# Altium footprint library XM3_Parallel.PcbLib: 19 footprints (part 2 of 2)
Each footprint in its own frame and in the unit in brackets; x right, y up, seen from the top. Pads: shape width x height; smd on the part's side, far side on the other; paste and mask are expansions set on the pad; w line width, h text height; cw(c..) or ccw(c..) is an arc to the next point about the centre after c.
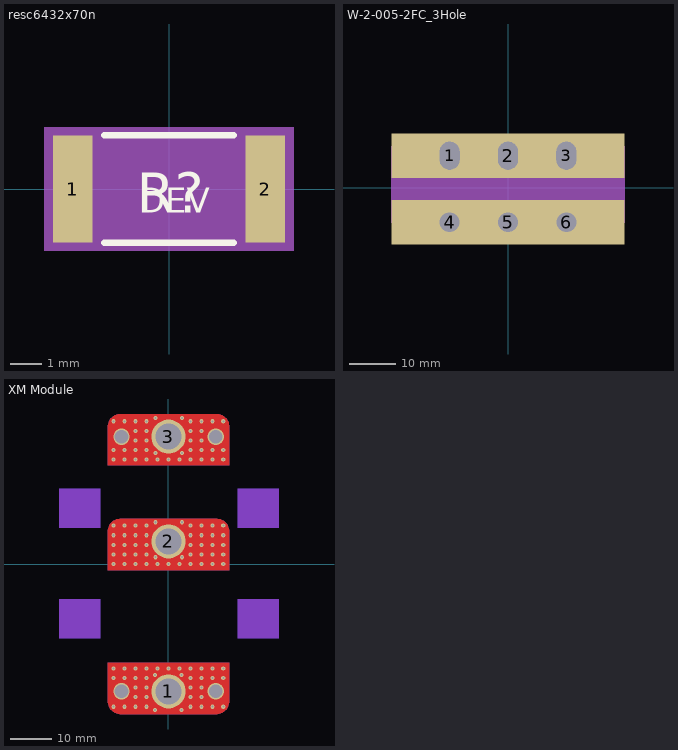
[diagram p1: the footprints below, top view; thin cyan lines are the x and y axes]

## resc6432x70n [mil]
pads (2):
  rect 49.21x133.86 smd: 1(-120.08,0) 2(120.08,0)
Top Overlay:
  lines w8: -80.71,-66.93 80.71,-66.93 ; -80.71,66.93 80.71,66.93
  text "DEV" at -37.2,-29.53 h31
  text "R?" at -40,-29.53 h50
DFA_BOUND_TOP:
  region: -155.51,-76.77 155.51,-76.77 155.51,76.77 -155.51,76.77
PLACE_BOUND_TOP:
  region: -155.51,-76.77 155.51,-76.77 155.51,76.77 -155.51,76.77
DISPLAY_TOP:
  lines w0.04: -129.92,-66.93 129.92,-66.93 129.92,66.93 -129.92,66.93 -129.92,-66.93
DRAWING_ORIGIN:
  lines w1: -25,0 25,0 ; 0,-25 0,25
PIN_NUMBER:
  text "1" at -140.08,0 h25
  text "2" at 100.08,0 h25
ASSEMBLY_TOP:
  lines w2: -129.92,-66.93 129.92,-66.93 129.92,66.93 -129.92,66.93 -129.92,-66.93
  text "R?" at -40,-29.53 h50
3D body: height 150, standoff 0, extent -155.51,-76.77 155.51,76.77

## W-2-005-2FC_3Hole [mil]
pads (6):
  oval 180x250 hole 170 slot 240 at 90 deg: 1(-500,275) 3(500,275)
  rect 2000x380 / inner oval 196.85x255.91 / far side rect 2000x380 hole 170 slot 240 at 90 deg: 2(0,275)
  round 200 hole 170: 4(-500,-295.28) 6(500,-295.28)
  rect 2000x380 / inner rect 0x0 / far side rect 2000x380 hole 170: 5(0,-295.28)
Top Solder:
  region: -1050,525 1050,525 1050,-550 -1050,-550
Bottom Solder:
  region: -1050,525 1050,525 1050,-550 -1050,-550
DRAWING_ORIGIN:
  lines w1: -25,75 25,75 ; 0,50 0,100
PIN_NUMBER:
  text "5" at 480,-300 h25
  text "4" at -20,-300 h25
  text "3" at -520,-300 h25
  text "5" at 480,275 h25
  text "4" at -20,275 h25
  text "3" at -520,275 h25
ASSEMBLY_DETAIL:
  dashed: 0,-300 0,355 -500,355 -500,-300
  dashed: 1000,-300 1000,355 500,355 500,-300
  dashed: 500,-300 500,355 0,355 0,-300
  dashed: -500,-300 -500,355 -1000,355 -1000,-300

## XM Module [mm]
pads (3):
  round 8.3 hole 6.3: 1(0,-31) 2(0,5.5) 3(0,31)
via -8.001,6.994 diameter 1 hole 0.5
via -13.335,25.4 diameter 1 hole 0.5
via 13.335,25.4 diameter 1 hole 0.5
via 8.001,25.4 diameter 1 hole 0.5
via 5.334,25.4 diameter 1 hole 0.5
via 2.667,25.4 diameter 1 hole 0.5
via 0,25.4 diameter 1 hole 0.5
via -2.667,25.4 diameter 1 hole 0.5
via -5.334,25.4 diameter 1 hole 0.5
via -8.001,25.4 diameter 1 hole 0.5
via -10.668,25.4 diameter 1 hole 0.5
via -13.335,27.731 diameter 1 hole 0.5
via 13.335,27.731 diameter 1 hole 0.5
via 8.001,27.731 diameter 1 hole 0.5
via 5.334,27.731 diameter 1 hole 0.5
via -5.334,27.731 diameter 1 hole 0.5
via -8.001,27.731 diameter 1 hole 0.5
via -10.668,27.731 diameter 1 hole 0.5
via 8.001,30.063 diameter 1 hole 0.5
via 5.334,30.063 diameter 1 hole 0.5
via -5.334,30.063 diameter 1 hole 0.5
via 8.001,32.394 diameter 1 hole 0.5
via 5.334,32.394 diameter 1 hole 0.5
via -5.334,32.394 diameter 1 hole 0.5
via -8.001,32.394 diameter 1 hole 0.5
via -8.001,34.725 diameter 1 hole 0.5
via -5.334,34.725 diameter 1 hole 0.5
via -13.335,34.725 diameter 1 hole 0.5
via -10.668,34.725 diameter 1 hole 0.5
via 5.334,34.725 diameter 1 hole 0.5
via 8.001,34.725 diameter 1 hole 0.5
via 3.3,35.56 diameter 1 hole 0.5
via -3.175,35.56 diameter 1 hole 0.5
via 13.335,34.725 diameter 1 hole 0.5
via -3.175,27.05 diameter 1 hole 0.5
via 3.3,27.05 diameter 1 hole 0.5
via 10.668,27.731 diameter 1 hole 0.5
via 10.668,25.4 diameter 1 hole 0.5
via 10.668,34.725 diameter 1 hole 0.5
via -8.001,30.063 diameter 1 hole 0.5
via 11.463,-31 diameter 4 hole 3.3
via -11.43,-31 diameter 4 hole 3.3
via -11.43,31 diameter 4 hole 3.3
via 13.335,-25.4 diameter 1 hole 0.5
via -13.335,-25.4 diameter 1 hole 0.5
via -8.001,-25.4 diameter 1 hole 0.5
via -5.334,-25.4 diameter 1 hole 0.5
via -2.667,-25.4 diameter 1 hole 0.5
via 0,-25.4 diameter 1 hole 0.5
via 2.667,-25.4 diameter 1 hole 0.5
via 5.334,-25.4 diameter 1 hole 0.5
via 8.001,-25.4 diameter 1 hole 0.5
via 10.668,-25.4 diameter 1 hole 0.5
via 13.335,-27.731 diameter 1 hole 0.5
via -13.335,-27.731 diameter 1 hole 0.5
via -8.001,-27.731 diameter 1 hole 0.5
via -5.334,-27.731 diameter 1 hole 0.5
via 5.334,-27.731 diameter 1 hole 0.5
via 8.001,-27.731 diameter 1 hole 0.5
via 10.668,-27.731 diameter 1 hole 0.5
via -8.001,-30.063 diameter 1 hole 0.5
via -5.334,-30.063 diameter 1 hole 0.5
via 5.334,-30.063 diameter 1 hole 0.5
via 8.001,-30.063 diameter 1 hole 0.5
via -8.001,-32.394 diameter 1 hole 0.5
via -5.334,-32.394 diameter 1 hole 0.5
via 5.334,-32.394 diameter 1 hole 0.5
via 8.001,-32.394 diameter 1 hole 0.5
via 8.001,-34.725 diameter 1 hole 0.5
via 5.334,-34.725 diameter 1 hole 0.5
via 13.335,-34.725 diameter 1 hole 0.5
via 10.668,-34.725 diameter 1 hole 0.5
via -5.334,-34.725 diameter 1 hole 0.5
via -8.001,-34.725 diameter 1 hole 0.5
via -3.3,-35.56 diameter 1 hole 0.5
via 3.175,-35.56 diameter 1 hole 0.5
via -13.335,-34.725 diameter 1 hole 0.5
via 3.175,-27.05 diameter 1 hole 0.5
via -3.3,-27.05 diameter 1 hole 0.5
via -10.668,-27.731 diameter 1 hole 0.5
via -10.668,-25.4 diameter 1 hole 0.5
via -10.668,-34.725 diameter 1 hole 0.5
via -13.335,0 diameter 1 hole 0.5
via 13.335,0 diameter 1 hole 0.5
via 8.001,0 diameter 1 hole 0.5
via 5.334,0 diameter 1 hole 0.5
via 2.667,0 diameter 1 hole 0.5
via 0,0 diameter 1 hole 0.5
via -2.667,0 diameter 1 hole 0.5
via -5.334,0 diameter 1 hole 0.5
via -8.001,0 diameter 1 hole 0.5
via -10.668,0 diameter 1 hole 0.5
via -13.335,2.331 diameter 1 hole 0.5
via 13.335,2.331 diameter 1 hole 0.5
via 8.001,2.331 diameter 1 hole 0.5
via 5.334,2.331 diameter 1 hole 0.5
via -5.334,2.331 diameter 1 hole 0.5
via -8.001,2.331 diameter 1 hole 0.5
via -10.668,2.331 diameter 1 hole 0.5
via -13.335,4.663 diameter 1 hole 0.5
via 13.335,4.663 diameter 1 hole 0.5
via 8.001,4.663 diameter 1 hole 0.5
via 5.334,4.663 diameter 1 hole 0.5
via -5.334,4.663 diameter 1 hole 0.5
via -8.001,4.663 diameter 1 hole 0.5
via -10.668,4.663 diameter 1 hole 0.5
via -13.335,6.994 diameter 1 hole 0.5
via 13.335,6.994 diameter 1 hole 0.5
via 8.001,6.994 diameter 1 hole 0.5
via 5.334,6.994 diameter 1 hole 0.5
via -5.334,6.994 diameter 1 hole 0.5
via -10.668,6.994 diameter 1 hole 0.5
via -8.001,9.325 diameter 1 hole 0.5
via -5.334,9.325 diameter 1 hole 0.5
via -13.335,9.325 diameter 1 hole 0.5
via -10.668,9.325 diameter 1 hole 0.5
via 5.334,9.325 diameter 1 hole 0.5
via 8.001,9.325 diameter 1 hole 0.5
via 3.3,10.16 diameter 1 hole 0.5
via -3.175,10.16 diameter 1 hole 0.5
via 13.335,9.325 diameter 1 hole 0.5
via -3.175,1.65 diameter 1 hole 0.5
via 3.3,1.65 diameter 1 hole 0.5
via 10.668,2.331 diameter 1 hole 0.5
via 10.668,0 diameter 1 hole 0.5
via 10.668,6.994 diameter 1 hole 0.5
via 10.668,4.663 diameter 1 hole 0.5
via 10.668,9.325 diameter 1 hole 0.5
via 11.463,31 diameter 4 hole 3.3
TOP:
  region: -14.75,-24 14.75,-24 14.75,-33.452 14.75,-33.652 14.698,-34.048 14.594,-34.434 14.442,-34.803 14.242,-35.149 13.999,-35.466 13.716,-35.749 13.399,-35.992 13.053,-36.192 12.684,-36.344 12.298,-36.448 11.902,-36.5 11.702,-36.5 -11.702,-36.5 -11.902,-36.5 -12.298,-36.448 -12.684,-36.344 -13.053,-36.192 -13.399,-35.992 -13.716,-35.749 -13.999,-35.466 -14.242,-35.149 -14.442,-34.803 -14.594,-34.434 -14.698,-34.048 -14.75,-33.652 -14.75,-33.452 -14.75,-25
  region: -14.75,-24 14.75,-24 14.75,-33.452 14.75,-33.652 14.698,-34.048 14.594,-34.434 14.442,-34.803 14.242,-35.149 13.999,-35.466 13.716,-35.749 13.399,-35.992 13.053,-36.192 12.684,-36.344 12.298,-36.448 11.902,-36.5 11.702,-36.5 -11.702,-36.5 -11.902,-36.5 -12.298,-36.448 -12.684,-36.344 -13.053,-36.192 -13.399,-35.992 -13.716,-35.749 -13.999,-35.466 -14.242,-35.149 -14.442,-34.803 -14.594,-34.434 -14.698,-34.048 -14.75,-33.652 -14.75,-33.452 -14.75,-25
  region: -14.75,24 14.768,24 14.768,33.452 14.768,33.652 14.716,34.048 14.612,34.434 14.459,34.803 14.259,35.149 14.016,35.466 13.734,35.749 13.417,35.992 13.071,36.192 12.702,36.344 12.316,36.448 11.919,36.5 11.72,36.5 -11.702,36.5 -11.902,36.5 -12.298,36.448 -12.684,36.344 -13.053,36.192 -13.399,35.992 -13.716,35.749 -13.999,35.466 -14.242,35.149 -14.442,34.803 -14.594,34.434 -14.698,34.048 -14.75,33.652 -14.75,33.452 -14.75,28.75
  region: -14.75,-1.5 14.75,-1.5 14.75,7.952 14.75,8.152 14.698,8.548 14.594,8.934 14.442,9.303 14.242,9.649 13.999,9.966 13.716,10.249 13.399,10.492 13.053,10.692 12.684,10.844 12.298,10.948 11.902,11 11.702,11 -11.702,11 -11.902,11 -12.298,10.948 -12.684,10.844 -13.053,10.692 -13.399,10.492 -13.716,10.249 -13.999,9.966 -14.242,9.649 -14.442,9.303 -14.594,8.934 -14.698,8.548 -14.75,8.152 -14.75,7.952 -14.75,2.236
TOP keep-out:
  rectangle: -26.67,8.801 -16.51,18.326
  rectangle: 16.764,8.801 26.924,18.326
  rectangle: 16.764,-18.098 26.924,-8.572
  rectangle: -26.67,-18.098 -16.51,-8.572
BOTTOM:
  region: -14.75,24 14.768,24 14.768,33.452 14.768,33.652 14.716,34.048 14.612,34.434 14.459,34.803 14.259,35.149 14.016,35.466 13.734,35.749 13.417,35.992 13.071,36.192 12.702,36.344 12.316,36.448 11.919,36.5 11.72,36.5 -11.702,36.5 -11.902,36.5 -12.298,36.448 -12.684,36.344 -13.053,36.192 -13.399,35.992 -13.716,35.749 -13.999,35.466 -14.242,35.149 -14.442,34.803 -14.594,34.434 -14.698,34.048 -14.75,33.652 -14.75,33.452 -14.75,28.75
  region: -14.75,-1.5 14.75,-1.5 14.75,7.952 14.75,8.152 14.698,8.548 14.594,8.934 14.442,9.303 14.242,9.649 13.999,9.966 13.716,10.249 13.399,10.492 13.053,10.692 12.684,10.844 12.298,10.948 11.902,11 11.702,11 -11.702,11 -11.902,11 -12.298,10.948 -12.684,10.844 -13.053,10.692 -13.399,10.492 -13.716,10.249 -13.999,9.966 -14.242,9.649 -14.442,9.303 -14.594,8.934 -14.698,8.548 -14.75,8.152 -14.75,7.952 -14.75,2.236
  region: -14.75,-24 14.75,-24 14.75,-33.452 14.75,-33.652 14.698,-34.048 14.594,-34.434 14.442,-34.803 14.242,-35.149 13.999,-35.466 13.716,-35.749 13.399,-35.992 13.053,-36.192 12.684,-36.344 12.298,-36.448 11.902,-36.5 11.702,-36.5 -11.702,-36.5 -11.902,-36.5 -12.298,-36.448 -12.684,-36.344 -13.053,-36.192 -13.399,-35.992 -13.716,-35.749 -13.999,-35.466 -14.242,-35.149 -14.442,-34.803 -14.594,-34.434 -14.698,-34.048 -14.75,-33.652 -14.75,-33.452 -14.75,-25
BOTTOM keep-out:
  rectangle: 16.764,8.801 26.924,18.326
  rectangle: 16.764,-18.098 26.924,-8.572
  rectangle: -26.67,-18.098 -16.51,-8.572
  rectangle: -26.67,8.801 -16.51,18.326
Top Solder:
  region: -14.75,-24 14.75,-24 14.75,-33.452 14.75,-33.652 14.698,-34.048 14.594,-34.434 14.442,-34.803 14.242,-35.149 13.999,-35.466 13.716,-35.749 13.399,-35.992 13.053,-36.192 12.684,-36.344 12.298,-36.448 11.902,-36.5 11.702,-36.5 -11.702,-36.5 -11.902,-36.5 -12.298,-36.448 -12.684,-36.344 -13.053,-36.192 -13.399,-35.992 -13.716,-35.749 -13.999,-35.466 -14.242,-35.149 -14.442,-34.803 -14.594,-34.434 -14.698,-34.048 -14.75,-33.652 -14.75,-33.452 -14.75,-25
  region: -14.75,24 14.768,24 14.768,33.452 14.768,33.652 14.716,34.048 14.612,34.434 14.459,34.803 14.259,35.149 14.016,35.466 13.734,35.749 13.417,35.992 13.071,36.192 12.702,36.344 12.316,36.448 11.919,36.5 11.72,36.5 -11.702,36.5 -11.902,36.5 -12.298,36.448 -12.684,36.344 -13.053,36.192 -13.399,35.992 -13.716,35.749 -13.999,35.466 -14.242,35.149 -14.442,34.803 -14.594,34.434 -14.698,34.048 -14.75,33.652 -14.75,33.452 -14.75,28.75
  region: -14.75,-1.5 14.75,-1.5 14.75,7.952 14.75,8.152 14.698,8.548 14.594,8.934 14.442,9.303 14.242,9.649 13.999,9.966 13.716,10.249 13.399,10.492 13.053,10.692 12.684,10.844 12.298,10.948 11.902,11 11.702,11 -11.702,11 -11.902,11 -12.298,10.948 -12.684,10.844 -13.053,10.692 -13.399,10.492 -13.716,10.249 -13.999,9.966 -14.242,9.649 -14.442,9.303 -14.594,8.934 -14.698,8.548 -14.75,8.152 -14.75,7.952 -14.75,2.236
Bottom Solder:
  region: -14.75,-24 14.75,-24 14.75,-33.452 14.75,-33.652 14.698,-34.048 14.594,-34.434 14.442,-34.803 14.242,-35.149 13.999,-35.466 13.716,-35.749 13.399,-35.992 13.053,-36.192 12.684,-36.344 12.298,-36.448 11.902,-36.5 11.702,-36.5 -11.702,-36.5 -11.902,-36.5 -12.298,-36.448 -12.684,-36.344 -13.053,-36.192 -13.399,-35.992 -13.716,-35.749 -13.999,-35.466 -14.242,-35.149 -14.442,-34.803 -14.594,-34.434 -14.698,-34.048 -14.75,-33.652 -14.75,-33.452 -14.75,-25
  region: -14.75,24 14.768,24 14.768,33.452 14.768,33.652 14.716,34.048 14.612,34.434 14.459,34.803 14.259,35.149 14.016,35.466 13.734,35.749 13.417,35.992 13.071,36.192 12.702,36.344 12.316,36.448 11.919,36.5 11.72,36.5 -11.702,36.5 -11.902,36.5 -12.298,36.448 -12.684,36.344 -13.053,36.192 -13.399,35.992 -13.716,35.749 -13.999,35.466 -14.242,35.149 -14.442,34.803 -14.594,34.434 -14.698,34.048 -14.75,33.652 -14.75,33.452 -14.75,28.75
  region: -14.75,-1.5 14.75,-1.5 14.75,7.952 14.75,8.152 14.698,8.548 14.594,8.934 14.442,9.303 14.242,9.649 13.999,9.966 13.716,10.249 13.399,10.492 13.053,10.692 12.684,10.844 12.298,10.948 11.902,11 11.702,11 -11.702,11 -11.902,11 -12.298,10.948 -12.684,10.844 -13.053,10.692 -13.399,10.492 -13.716,10.249 -13.999,9.966 -14.242,9.649 -14.442,9.303 -14.594,8.934 -14.698,8.548 -14.75,8.152 -14.75,7.952 -14.75,2.236
Keep-Out Layer:
  board cut-out: 17.145,18.034 26.67,18.034 26.67,9.144 17.145,9.144
  board cut-out: 17.145,-8.89 26.67,-8.89 26.67,-17.78 17.145,-17.78
  board cut-out: -26.352,-8.89 -16.828,-8.89 -16.828,-17.78 -26.352,-17.78
  board cut-out: -26.352,18.034 -16.828,18.034 -16.828,9.144 -26.352,9.144
3D body "Wolfspeed_XM3_Power_Module.step": height 15.76, standoff -2.5, extent -26.5,-40 26.5,40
